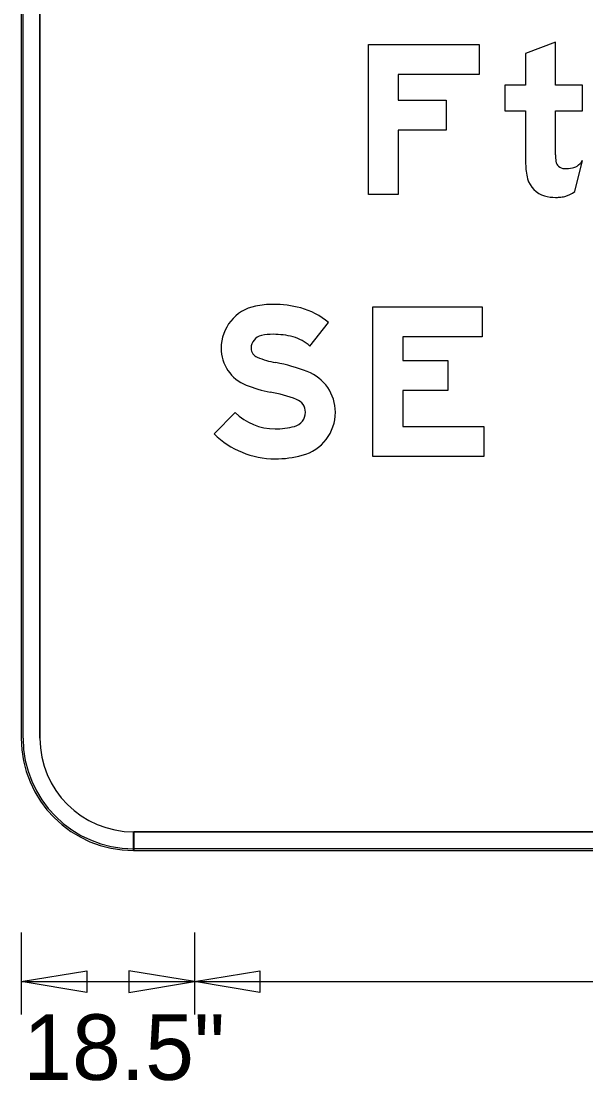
# Model space of a CAD drawing. Extents: x 2149961 to 2150220, y 145114 to 145240.
# Drawn here: x 2150197.47 to 2150202.5, y 145128.27 to 145137.7 of the extents above; entities that cross this region are included whole.
import ezdxf

# ---------------------------------------------------------------- set-up
doc = ezdxf.new("R2010")
doc.units = 0
for name, color, linetype in [('GSBWFILL', 7, 'Continuous'), ('GSCOLORFILL', 7, 'Continuous'), ('GSDIMS', 7, 'Continuous'), ('GSOUTLINE', 7, 'Continuous')]:
    doc.layers.add(name, color=color, linetype=linetype)

msp = doc.modelspace()

# ---------------------------------------------------------------- linework, layer by layer
at = {"layer": 'GSBWFILL'}
for p, q in [((2150197.4727, 145145.8166), (2150197.4727, 145131.3166)), ((2150197.6393, 145131.3166), (2150197.6393, 145145.8166)), ((2150202.3985, 145136.1831), (2150202.4687, 145136.4591)), ((2150198.4727, 145130.3166), (2150198.4727, 145130.4833)), ((2150211.9727, 145130.4833), (2150198.4743, 145130.4833)), ((2150198.4743, 145130.4833), (2150198.4743, 145130.3166)), ((2150198.4743, 145130.3166), (2150211.9727, 145130.3166))]:
    msp.add_line(p, q, dxfattribs=at)
for points in [[(2150200.562, 145137.4916), (2150201.5487, 145137.4916), (2150201.5487, 145137.225), (2150200.8287, 145137.225), (2150200.8287, 145136.9983), (2150201.2553, 145136.9983), (2150201.2553, 145136.7316), (2150200.8287, 145136.7316), (2150200.8287, 145136.1583), (2150200.562, 145136.1583)], [(2150201.5753, 145135.1583), (2150201.5753, 145134.8916), (2150200.8687, 145134.8916), (2150200.8687, 145134.6783), (2150201.2687, 145134.6783), (2150201.2687, 145134.4116), (2150200.8687, 145134.4116), (2150200.8687, 145134.0916), (2150201.5887, 145134.0916), (2150201.5887, 145133.825), (2150200.602, 145133.825), (2150200.602, 145135.1583)]]:
    msp.add_lwpolyline(points, close=True, dxfattribs=at)
for points in [[(2150202.2287, 145136.5116), (2150202.2287, 145136.9016), (2150202.4687, 145136.9016), (2150202.4687, 145137.1316), (2150202.2287, 145137.1316), (2150202.2287, 145137.515), (2150201.962, 145137.4138), (2150201.962, 145137.1316), (2150201.7753, 145137.1316), (2150201.7753, 145136.9016), (2150201.962, 145136.9016), (2150201.962, 145136.431)], [(2150200.0421, 145134.8063), (2150200.207, 145135.0168)], [(2150199.3764, 145134.2168), (2150199.1887, 145134.0274)]]:
    msp.add_lwpolyline(points, dxfattribs=at)
for radius in [1, 0.8333]:
    msp.add_arc((2150198.4727, 145131.3166), radius, 180, 270, dxfattribs=at)
for centre, major_axis, start_param, end_param in [((2150203.8979, 145136.5116), (0, 1.6693), 1.570796, 1.606005), ((2150202.4794, 145136.431), (0, 0.5174), 1.570796, 1.830698), ((2150202.3052, 145136.4658), (0, 0.0767), 1.74085, 2.407828), ((2150202.3077, 145136.4685), (0, 0.0803), 2.407828, 3.141593), ((2150202.3617, 145136.4928), (0, 0.1), 3.310762, 3.756278), ((2150202.2931, 145136.59), (0, 0.2189), 3.756278, 4.071638), ((2150202.3077, 145136.8094), (0, 0.4211), 3.141593, 3.310762), ((2150202.1888, 145136.3537), (0, 0.2167), 1.830698, 2.869526), ((2150202.2286, 145136.4967), (0, 0.3651), 2.869526, 3.141593), ((2150202.2286, 145136.6575), (0, 0.5258), 3.141593, 3.205734), ((2150202.2485, 145136.3489), (0, 0.2167), 3.205734, 3.427755), ((2150202.2201, 145136.4454), (0, 0.3172), 3.427755, 3.738844), ((2150199.7153, 145134.3938), (0, 0.7855), 0, 0.202758), ((2150199.7153, 145134.2161), (0, 0.9632), 6.026234, 6.283185), ((2150199.6341, 145134.7891), (0, 0.382), 0.202758, 1.570796), ((2150199.8047, 145134.5562), (0, 0.6115), 5.565152, 6.026234), ((2150199.6341, 145134.7891), (0, 0.1153), 0.202758, 1.570796), ((2150199.7153, 145134.3938), (0, 0.5188), 0, 0.202758), ((2150199.7153, 145134.2161), (0, 0.6965), 6.026234, 6.283185), ((2150199.8047, 145134.5562), (0, 0.3448), 5.523837, 6.026234), ((2150199.6059, 145134.7891), (0, 0.3538), 1.570796, 2.761249), ((2150199.6059, 145134.7891), (0, 0.0872), 1.570796, 2.761249), ((2150199.8965, 145135.5159), (0, 0.8699), 2.761249, 2.95744), ((2150199.44, 145133.0648), (0, 1.6233), 5.918637, 6.099033), ((2150199.8802, 145134.2185), (0, 0.3885), 4.712389, 5.918637), ((2150199.8965, 145135.5159), (0, 1.1366), 2.761249, 2.95744), ((2150199.44, 145133.0648), (0, 1.3566), 5.918637, 6.099033), ((2150199.8802, 145134.2185), (0, 0.1218), 4.712389, 5.918637), ((2150199.7315, 145134.5751), (0, 0.5044), 2.360607, 3.141593), ((2150199.8726, 145134.2185), (0, 0.1295), 3.401517, 4.712389), ((2150199.8726, 145134.2185), (0, 0.3961), 3.401517, 4.712389), ((2150199.7315, 145134.7488), (0, 0.6782), 3.141593, 3.401517), ((2150199.7315, 145134.5751), (0, 0.7711), 2.360607, 3.141593), ((2150199.7315, 145134.7488), (0, 0.9449), 3.141593, 3.401517)]:
    msp.add_ellipse(centre, major_axis=major_axis, ratio=0.999994, start_param=start_param, end_param=end_param, dxfattribs=at)
at = {"layer": 'GSCOLORFILL'}
for p, q in [((2150197.4727, 145145.8166), (2150197.4727, 145131.3166)), ((2150197.4727, 145145.8166), (2150197.4727, 145131.3166)), ((2150197.4727, 145145.8166), (2150197.4727, 145131.3166)), ((2150197.4893, 145131.3166), (2150197.4893, 145145.8166)), ((2150197.6393, 145131.3166), (2150197.6393, 145145.8166)), ((2150202.3985, 145136.1831), (2150202.4687, 145136.4591)), ((2150198.4727, 145130.3166), (2150198.4727, 145130.4833)), ((2150211.9727, 145130.4833), (2150198.4743, 145130.4833)), ((2150198.4743, 145130.4833), (2150198.4743, 145130.3166)), ((2150198.4727, 145130.3166), (2150198.4727, 145130.3333)), ((2150198.4727, 145130.3166), (2150211.9727, 145130.3166)), ((2150211.9727, 145130.3333), (2150198.4728, 145130.3333)), ((2150198.4728, 145130.3333), (2150198.4728, 145130.3166)), ((2150198.4728, 145130.3166), (2150211.9727, 145130.3166)), ((2150198.4743, 145130.3166), (2150211.9727, 145130.3166))]:
    msp.add_line(p, q, dxfattribs=at)
for points in [[(2150200.562, 145137.4916), (2150201.5487, 145137.4916), (2150201.5487, 145137.225), (2150200.8287, 145137.225), (2150200.8287, 145136.9983), (2150201.2553, 145136.9983), (2150201.2553, 145136.7316), (2150200.8287, 145136.7316), (2150200.8287, 145136.1583), (2150200.562, 145136.1583)], [(2150201.5753, 145135.1583), (2150201.5753, 145134.8916), (2150200.8687, 145134.8916), (2150200.8687, 145134.6783), (2150201.2687, 145134.6783), (2150201.2687, 145134.4116), (2150200.8687, 145134.4116), (2150200.8687, 145134.0916), (2150201.5887, 145134.0916), (2150201.5887, 145133.825), (2150200.602, 145133.825), (2150200.602, 145135.1583)]]:
    msp.add_lwpolyline(points, close=True, dxfattribs=at)
for points in [[(2150202.2287, 145136.5116), (2150202.2287, 145136.9016), (2150202.4687, 145136.9016), (2150202.4687, 145137.1316), (2150202.2287, 145137.1316), (2150202.2287, 145137.515), (2150201.962, 145137.4138), (2150201.962, 145137.1316), (2150201.7753, 145137.1316), (2150201.7753, 145136.9016), (2150201.962, 145136.9016), (2150201.962, 145136.431)], [(2150200.0421, 145134.8063), (2150200.207, 145135.0168)], [(2150199.3764, 145134.2168), (2150199.1887, 145134.0274)]]:
    msp.add_lwpolyline(points, dxfattribs=at)
for radius in [1, 1, 1, 0.9833, 0.8333]:
    msp.add_arc((2150198.4727, 145131.3166), radius, 180, 270, dxfattribs=at)
for centre, major_axis, start_param, end_param in [((2150203.8979, 145136.5116), (0, 1.6693), 1.570796, 1.606005), ((2150202.4794, 145136.431), (0, 0.5174), 1.570796, 1.830698), ((2150202.3052, 145136.4658), (0, 0.0767), 1.74085, 2.407828), ((2150202.3077, 145136.4685), (0, 0.0803), 2.407828, 3.141593), ((2150202.3617, 145136.4928), (0, 0.1), 3.310762, 3.756278), ((2150202.2931, 145136.59), (0, 0.2189), 3.756278, 4.071638), ((2150202.3077, 145136.8094), (0, 0.4211), 3.141593, 3.310762), ((2150202.1888, 145136.3537), (0, 0.2167), 1.830698, 2.869526), ((2150202.2286, 145136.4967), (0, 0.3651), 2.869526, 3.141593), ((2150202.2286, 145136.6575), (0, 0.5258), 3.141593, 3.205734), ((2150202.2485, 145136.3489), (0, 0.2167), 3.205734, 3.427755), ((2150202.2201, 145136.4454), (0, 0.3172), 3.427755, 3.738844), ((2150199.7153, 145134.3938), (0, 0.7855), 0, 0.202758), ((2150199.7153, 145134.2161), (0, 0.9632), 6.026234, 6.283185), ((2150199.6341, 145134.7891), (0, 0.382), 0.202758, 1.570796), ((2150199.8047, 145134.5562), (0, 0.6115), 5.565152, 6.026234), ((2150199.6341, 145134.7891), (0, 0.1153), 0.202758, 1.570796), ((2150199.7153, 145134.3938), (0, 0.5188), 0, 0.202758), ((2150199.7153, 145134.2161), (0, 0.6965), 6.026234, 6.283185), ((2150199.8047, 145134.5562), (0, 0.3448), 5.523837, 6.026234), ((2150199.6059, 145134.7891), (0, 0.3538), 1.570796, 2.761249), ((2150199.6059, 145134.7891), (0, 0.0872), 1.570796, 2.761249), ((2150199.8965, 145135.5159), (0, 0.8699), 2.761249, 2.95744), ((2150199.44, 145133.0648), (0, 1.6233), 5.918637, 6.099033), ((2150199.8802, 145134.2185), (0, 0.3885), 4.712389, 5.918637), ((2150199.8965, 145135.5159), (0, 1.1366), 2.761249, 2.95744), ((2150199.44, 145133.0648), (0, 1.3566), 5.918637, 6.099033), ((2150199.8802, 145134.2185), (0, 0.1218), 4.712389, 5.918637), ((2150199.7315, 145134.5751), (0, 0.5044), 2.360607, 3.141593), ((2150199.8726, 145134.2185), (0, 0.1295), 3.401517, 4.712389), ((2150199.8726, 145134.2185), (0, 0.3961), 3.401517, 4.712389), ((2150199.7315, 145134.7488), (0, 0.6782), 3.141593, 3.401517), ((2150199.7315, 145134.5751), (0, 0.7711), 2.360607, 3.141593), ((2150199.7315, 145134.7488), (0, 0.9449), 3.141593, 3.401517)]:
    msp.add_ellipse(centre, major_axis=major_axis, ratio=0.999994, start_param=start_param, end_param=end_param, dxfattribs=at)
at = {"layer": 'GSDIMS'}
for p, q in [((2150197.4726, 145129.5874), (2150197.4726, 145128.8582)), ((2150197.4726, 145129.5874), (2150197.4726, 145128.8582)), ((2150199.0142, 145129.5874), (2150199.0142, 145128.8582)), ((2150199.0142, 145129.5874), (2150199.0142, 145128.8582)), ((2150197.4726, 145129.1499), (2150199.0142, 145129.1499)), ((2150199.0142, 145129.1499), (2150211.4311, 145129.1499))]:
    msp.add_line(p, q, dxfattribs=at)
for points in [[(2150197.4726, 145129.1499), (2150198.056, 145129.2471), (2150198.056, 145129.0527)], [(2150199.0142, 145129.1499), (2150198.4309, 145129.2471), (2150198.4309, 145129.0527)], [(2150199.0142, 145129.1499), (2150199.5976, 145129.2471), (2150199.5976, 145129.0527)]]:
    msp.add_lwpolyline(points, close=True, dxfattribs=at)
at = {"layer": 'GSOUTLINE'}
for p, q in [((2150197.4727, 145145.8166), (2150197.4727, 145131.3166)), ((2150197.6393, 145145.8166), (2150197.6393, 145131.3166)), ((2150202.3985, 145136.1831), (2150202.4687, 145136.4591)), ((2150198.4727, 145130.4833), (2150211.9727, 145130.4833)), ((2150198.4727, 145130.3166), (2150211.9727, 145130.3166))]:
    msp.add_line(p, q, dxfattribs=at)
for points in [[(2150200.562, 145137.4916), (2150201.5487, 145137.4916), (2150201.5487, 145137.225), (2150200.8287, 145137.225), (2150200.8287, 145136.9983), (2150201.2553, 145136.9983), (2150201.2553, 145136.7316), (2150200.8287, 145136.7316), (2150200.8287, 145136.1583), (2150200.562, 145136.1583)], [(2150201.5753, 145135.1583), (2150201.5753, 145134.8916), (2150200.8687, 145134.8916), (2150200.8687, 145134.6783), (2150201.2687, 145134.6783), (2150201.2687, 145134.4116), (2150200.8687, 145134.4116), (2150200.8687, 145134.0916), (2150201.5887, 145134.0916), (2150201.5887, 145133.825), (2150200.602, 145133.825), (2150200.602, 145135.1583)]]:
    msp.add_lwpolyline(points, close=True, dxfattribs=at)
for points in [[(2150202.2287, 145136.5116), (2150202.2287, 145136.9016), (2150202.4687, 145136.9016), (2150202.4687, 145137.1316), (2150202.2287, 145137.1316), (2150202.2287, 145137.515), (2150201.962, 145137.4138), (2150201.962, 145137.1316), (2150201.7753, 145137.1316), (2150201.7753, 145136.9016), (2150201.962, 145136.9016), (2150201.962, 145136.431)], [(2150200.0421, 145134.8063), (2150200.207, 145135.0168)], [(2150199.3764, 145134.2168), (2150199.1887, 145134.0274)]]:
    msp.add_lwpolyline(points, dxfattribs=at)
for radius in [1, 0.8333]:
    msp.add_arc((2150198.4727, 145131.3166), radius, 180, 270, dxfattribs=at)
for centre, major_axis, start_param, end_param in [((2150203.8979, 145136.5116), (0, 1.6693), 1.570796, 1.606005), ((2150202.4794, 145136.431), (0, 0.5174), 1.570796, 1.830698), ((2150202.3052, 145136.4658), (0, 0.0767), 1.74085, 2.407828), ((2150202.3077, 145136.4685), (0, 0.0803), 2.407828, 3.141593), ((2150202.3617, 145136.4928), (0, 0.1), 3.310762, 3.756278), ((2150202.2931, 145136.59), (0, 0.2189), 3.756278, 4.071638), ((2150202.3077, 145136.8094), (0, 0.4211), 3.141593, 3.310762), ((2150202.1888, 145136.3537), (0, 0.2167), 1.830698, 2.869526), ((2150202.2286, 145136.4967), (0, 0.3651), 2.869526, 3.141593), ((2150202.2286, 145136.6575), (0, 0.5258), 3.141593, 3.205734), ((2150202.2485, 145136.3489), (0, 0.2167), 3.205734, 3.427755), ((2150202.2201, 145136.4454), (0, 0.3172), 3.427755, 3.738844), ((2150199.7153, 145134.3938), (0, 0.7855), 0, 0.202758), ((2150199.7153, 145134.2161), (0, 0.9632), 6.026234, 6.283185), ((2150199.6341, 145134.7891), (0, 0.382), 0.202758, 1.570796), ((2150199.8047, 145134.5562), (0, 0.6115), 5.565152, 6.026234), ((2150199.6341, 145134.7891), (0, 0.1153), 0.202758, 1.570796), ((2150199.7153, 145134.3938), (0, 0.5188), 0, 0.202758), ((2150199.7153, 145134.2161), (0, 0.6965), 6.026234, 6.283185), ((2150199.8047, 145134.5562), (0, 0.3448), 5.523837, 6.026234), ((2150199.6059, 145134.7891), (0, 0.3538), 1.570796, 2.761249), ((2150199.6059, 145134.7891), (0, 0.0872), 1.570796, 2.761249), ((2150199.8965, 145135.5159), (0, 0.8699), 2.761249, 2.95744), ((2150199.44, 145133.0648), (0, 1.6233), 5.918637, 6.099033), ((2150199.8802, 145134.2185), (0, 0.3885), 4.712389, 5.918637), ((2150199.8965, 145135.5159), (0, 1.1366), 2.761249, 2.95744), ((2150199.44, 145133.0648), (0, 1.3566), 5.918637, 6.099033), ((2150199.8802, 145134.2185), (0, 0.1218), 4.712389, 5.918637), ((2150199.7315, 145134.5751), (0, 0.5044), 2.360607, 3.141593), ((2150199.8726, 145134.2185), (0, 0.1295), 3.401517, 4.712389), ((2150199.8726, 145134.2185), (0, 0.3961), 3.401517, 4.712389), ((2150199.7315, 145134.7488), (0, 0.6782), 3.141593, 3.401517), ((2150199.7315, 145134.5751), (0, 0.7711), 2.360607, 3.141593), ((2150199.7315, 145134.7488), (0, 0.9449), 3.141593, 3.401517)]:
    msp.add_ellipse(centre, major_axis=major_axis, ratio=0.999994, start_param=start_param, end_param=end_param, dxfattribs=at)

# ---------------------------------------------------------------- texts
at = {"layer": 'GSDIMS'}
msp.add_text('18.5"', height=0.58333, dxfattribs=at).set_placement((2150197.4914, 145128.2749))

doc.saveas('drawing.dxf')
